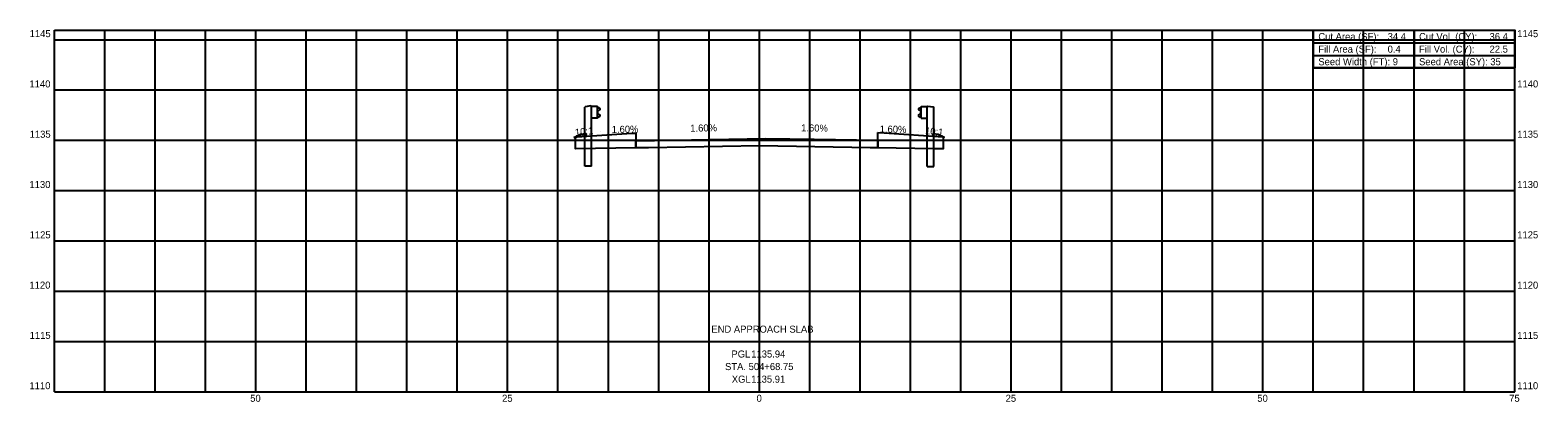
# Model space of a CAD drawing. Extents: x -72 to 77, y 1109 to 1146.
import ezdxf

# ---------------------------------------------------------------- set-up
doc = ezdxf.new("R2010")
doc.units = 0
for name, color, linetype in [('Default', 7, 'Continuous'), ('DT_P_Break_Line', 7, 'Continuous'), ('DT_P_Contour_Major', 7, 'Continuous'), ('DT_P_Contour_Minor', 7, 'Continuous'), ('DT_P_Contour_Text', 7, 'Continuous'), ('DT_P_Terrain_Boundary', 7, 'Continuous'), ('DT_X_Spot_Elev', 7, 'Continuous'), ('MD_X_Asphalt_Pavement_Removed', 7, 'Continuous')]:
    doc.layers.add(name, color=color, linetype=linetype)

msp = doc.modelspace()

# ---------------------------------------------------------------- linework, layer by layer
at = {"layer": 'Default'}
msp.add_circle((75, 1145.94), 0.000417, dxfattribs=at)
msp.add_circle((75, 1145.94), 0.000417, dxfattribs=at)
msp.add_circle((75, 1145.94), 0.000417, dxfattribs=at)
msp.add_circle((75, 1145.94), 0.000417, dxfattribs=at)
msp.add_circle((75, 1145.94), 0.000417, dxfattribs=at)
msp.add_circle((75, 1145.94), 0.000417, dxfattribs=at)
msp.add_circle((75, 1145.94), 0.000417, dxfattribs=at)
msp.add_circle((75, 1145.94), 0.000417, dxfattribs=at)
msp.add_circle((75, 1145.94), 0.000417, dxfattribs=at)
msp.add_circle((75, 1145.94), 0.000417, dxfattribs=at)
msp.add_circle((75, 1145.94), 0.000417, dxfattribs=at)
msp.add_circle((75, 1145.94), 0.000417, dxfattribs=at)
at = {"layer": 'DT_P_Break_Line'}
for p, q in [((-16, 1138.27), (-16.09, 1138.28)), ((-16.08, 1137.77), (-16.08, 1137.82)), ((-16.08, 1137.72), (-16.08, 1137.77)), ((-16.04, 1137.88), (-15.84, 1138.02)), ((-15.84, 1138.15), (-16, 1138.27)), ((15.81, 1138.15), (15.98, 1138.26)), ((16.02, 1137.88), (15.81, 1138.02)), ((15.98, 1138.26), (16.06, 1138.28)), ((16.05, 1137.77), (16.05, 1137.81)), ((-16.09, 1137.26), (-16, 1137.28)), ((-15.84, 1137.52), (-16.04, 1137.66)), ((-16, 1137.28), (-15.84, 1137.39)), ((15.81, 1137.51), (16.02, 1137.66)), ((15.98, 1137.27), (15.81, 1137.39)), ((16.06, 1137.26), (15.98, 1137.27)), ((16.05, 1137.72), (16.05, 1137.77))]:
    msp.add_line(p, q, dxfattribs=at)
for centre, start, end in [((-16, 1137.82), 124.962, 180), ((-15.88, 1138.09), 304.962, 54.7677), ((15.86, 1138.09), 125.2323, 235.038), ((15.97, 1137.81), 0, 55.038), ((-16, 1137.72), 180, 235.038), ((-15.88, 1137.45), 304.962, 54.7677), ((15.86, 1137.45), 125.2323, 235.038), ((15.97, 1137.72), 304.962, 0)]:
    msp.add_arc(centre, 0.0781, start, end, dxfattribs=at)
at = {"layer": 'DT_P_Contour_Major'}
msp.add_lwpolyline([(55, 1145.94), (75, 1145.94), (75, 1142.19), (55, 1142.19)], close=True, dxfattribs=at)
at = {"layer": 'DT_P_Contour_Text'}
for p, q in [((-70, 1145.94), (75, 1145.94)), ((-70, 1110), (-70, 1145.94)), ((-65, 1110), (-65, 1145.94)), ((-60, 1110), (-60, 1145.94)), ((-55, 1110), (-55, 1145.94)), ((-50, 1110), (-50, 1145.94)), ((-45, 1110), (-45, 1145.94)), ((-40, 1110), (-40, 1145.94)), ((-35, 1110), (-35, 1145.94)), ((-30, 1110), (-30, 1145.94)), ((-25, 1110), (-25, 1145.94)), ((-20, 1110), (-20, 1145.94)), ((-15, 1110), (-15, 1145.94)), ((-10, 1110), (-10, 1145.94)), ((-5, 1110), (-5, 1145.94)), ((0, 1110), (0, 1145.94)), ((5, 1110), (5, 1145.94)), ((10, 1110), (10, 1145.94)), ((15, 1110), (15, 1145.94)), ((20, 1110), (20, 1145.94)), ((25, 1110), (25, 1145.94)), ((30, 1110), (30, 1145.94)), ((35, 1110), (35, 1145.94)), ((40, 1110), (40, 1145.94)), ((45, 1110), (45, 1145.94)), ((50, 1110), (50, 1145.94)), ((55, 1110), (55, 1145.94)), ((60, 1110), (60, 1145.94)), ((65, 1110), (65, 1145.94)), ((70, 1110), (70, 1145.94)), ((75, 1110), (75, 1145.94)), ((-70, 1145), (75, 1145)), ((-70, 1140), (75, 1140)), ((-70, 1135), (75, 1135)), ((-70, 1130), (75, 1130)), ((-70, 1125), (75, 1125)), ((-70, 1120), (75, 1120)), ((-70, 1115), (75, 1115)), ((-70, 1110), (75, 1110))]:
    msp.add_line(p, q, dxfattribs=at)
at = {"layer": 'DT_P_Terrain_Boundary'}
for p, q in [((55, 1145.94), (75, 1145.94)), ((55, 1145.94), (55, 1143.44)), ((65, 1145.94), (65, 1142.19)), ((75, 1145.94), (75, 1143.44)), ((55, 1144.69), (75, 1144.69)), ((55, 1143.44), (75, 1143.44)), ((63.3, 1142.81), (63.3, 1142.81)), ((72.95, 1142.81), (72.95, 1142.81))]:
    msp.add_line(p, q, dxfattribs=at)
msp.add_lwpolyline([(55, 1143.44), (55, 1142.19), (75, 1142.19), (75, 1143.44)], dxfattribs=at)
at = {"layer": 'DT_X_Spot_Elev'}
for p, q in [((-17.29, 1138.32), (-17.34, 1138.3)), ((-17.34, 1132.41), (-17.34, 1138.3)), ((-16.75, 1138.41), (-17.29, 1138.32)), ((-16.67, 1138.36), (-16.75, 1138.41)), ((-16.09, 1138.36), (-16.67, 1138.36)), ((-16.67, 1132.41), (-16.67, 1138.36)), ((-16.09, 1137.2), (-16.09, 1138.37)), ((16.06, 1137.2), (16.06, 1138.36)), ((16.06, 1138.36), (16.65, 1138.36)), ((16.65, 1138.36), (16.73, 1138.4)), ((16.65, 1132.4), (16.65, 1138.36)), ((16.73, 1138.4), (17.26, 1138.32)), ((17.26, 1138.32), (17.31, 1138.3)), ((17.31, 1132.4), (17.31, 1138.3)), ((-16.09, 1137.2), (-16.67, 1137.2)), ((16.06, 1137.19), (16.65, 1137.19)), ((-15.81, 1135.86), (-15.81, 1135.86)), ((15.78, 1135.86), (15.78, 1135.86)), ((-16.67, 1132.41), (-17.34, 1132.41)), ((16.65, 1132.4), (17.31, 1132.4))]:
    msp.add_line(p, q, dxfattribs=at)
for points in [[(-16.07, 1137.83), (-16.07, 1137.71), (-16.08, 1137.71), (-16.08, 1137.83)], [(-16.07, 1137.8), (-16.07, 1137.74), (-16.04, 1137.74), (-16.04, 1137.8)], [(16.04, 1137.8), (16.04, 1137.74), (16.02, 1137.74), (16.02, 1137.8)], [(16.04, 1137.83), (16.04, 1137.71), (16.05, 1137.71), (16.05, 1137.83)]]:
    msp.add_lwpolyline(points, close=True, dxfattribs=at)
at = {"layer": 'MD_X_Asphalt_Pavement_Removed'}
for points in [[(-18.44, 1135.27), (-17.75, 1135.61), (-17.25, 1135.66), (-17.25, 1135.4), (-17.64, 1135.37), (-18.07, 1135.36), (-18.19, 1135.32)], [(-18.25, 1135.31), (-18.19, 1135.32), (-18.07, 1135.36), (-17.64, 1135.37), (-12.67, 1135.7), (-12.27, 1135.7), (-12.27, 1134.24), (-18.25, 1134.15)], [(-12.27, 1134.24), (-12.27, 1134.95), (0.65, 1135.18), (5.43, 1135.11), (11.77, 1135.02), (11.77, 1134.25), (11, 1134.26), (0, 1134.44), (-11, 1134.26)], [(11.77, 1135.77), (12.4, 1135.74), (18.25, 1135.33), (18.25, 1134.15), (17.25, 1134.16), (11.77, 1134.25)], [(17.25, 1135.66), (17.75, 1135.61), (18.33, 1135.32), (17.25, 1135.4)]]:
    msp.add_lwpolyline(points, close=True, dxfattribs=at)

# ---------------------------------------------------------------- texts
at = {"layer": 'DT_P_Contour_Minor'}
for s, p in [('1145', (-72.46, 1145.25)), ('Cut Area (SF):', (55.5, 1144.96)), ('34.4', (62.38, 1144.96)), ('Cut Vol. (CY):', (65.5, 1144.96)), ('36.4', (72.5, 1144.96)), ('1145', (75.25, 1145.25)), ('Fill Area (SF):', (55.5, 1143.71)), ('0.4', (62.38, 1143.71)), ('Fill Vol. (CY):', (65.5, 1143.71)), ('22.5', (72.5, 1143.71)), ('Seed Width (FT): 9', (55.5, 1142.46)), ('Seed Area (SY): 35', (65.5, 1142.46)), ('1140', (-72.48, 1140.25)), ('1140', (75.25, 1140.25)), ('1135', (-72.46, 1135.25)), ('1135', (75.25, 1135.25)), ('1130', (-72.48, 1130.25)), ('1130', (75.25, 1130.25)), ('1125', (-72.46, 1125.25)), ('1125', (75.25, 1125.25)), ('1120', (-72.48, 1120.25)), ('1120', (75.25, 1120.25)), ('1115', (-72.46, 1115.25)), ('END APPROACH SLAB', (-4.77, 1115.87)), ('1115', (75.25, 1115.25)), ('PGL ', (-2.78, 1113.4)), ('1135.94', (-0.81, 1113.4)), ('STA. 504+68.75', (-3.41, 1112.15)), ('1110', (-72.48, 1110.25)), ('XGL ', (-2.74, 1110.9)), ('1135.91', (-0.82, 1110.9)), ('1110', (75.25, 1110.25)), ('50', (-50.56, 1109)), ('25', (-25.55, 1109)), ('0', (-0.28, 1109)), ('25', (24.45, 1109)), ('50', (49.44, 1109)), ('75', (74.45, 1109))]:
    msp.add_text(s, height=0.7, dxfattribs=at).set_placement(p)
for s, rotation, p in [('10:1', 5.7106, (-18.28, 1135.43)), ('1.60%', 0.9167, (-14.66, 1135.72)), ('1.60%', 0.9167, (-6.86, 1135.85)), ('1.60%', 359.0833, (4.14, 1135.89)), ('1.60%', 359.0833, (11.94, 1135.77)), ('10:1', 354.2894, (16.42, 1135.62))]:
    msp.add_text(s, height=0.7, rotation=rotation, dxfattribs=at).set_placement(p)

doc.saveas('drawing.dxf')
